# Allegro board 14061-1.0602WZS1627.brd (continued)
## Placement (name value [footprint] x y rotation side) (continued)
C4289  SC10U10V5KX-2DLGP  [C805H50]  120.18 18.92 270 bottom
C4290  SCD1U16V2KX-3DLGP  [C402H22]  129.74 41.54 0 top
C4291  SCD1U16V2KX-3DLGP  [C402H22]  138.96 38.69 270 top
C4292  SCD1U16V2KX-3DLGP  [C402H22]  138.96 37.81 270 top
C4293  SCD1U16V2KX-3DLGP  [C402H22]  138.96 36 270 top
C4294  SCD1U16V2KX-3DLGP  [C402H22]  138.96 33.28 270 top
C4295  SCD1U16V2KX-3DLGP  [C402H22]  138.96 32.39 270 top
C4296  SCD1U16V2KX-3DLGP  [C402H22]  138.96 34.2 270 top
C4297  SCD1U16V2KX-3DLGP  [C402H22]  138.96 36.89 270 top
C4298  SCD1U16V2KX-3DLGP  [C402H22]  138.96 35.09 270 top
C6701  SCD1U16V2KX-3DLGP  [C402H22]  81.77 78.05 180 top
C6702  SCD1U16V2KX-3DLGP  [C402H22]  87.28 79.86 180 top
C6703  SC10U6D3V3MX-GP  [C603H38]  86.32 74.17 90 top
C6710  SC10U6D3V3MX-DL-GP  [C603H36]  48.42 117.73 270 top
C6711  SCD1U16V2KX-3DLGP  [C402H22]  48.67 104.01 270 top
C6715  SC10P50V2JN-4GP  [C402H22]  30.5 7.03 0 top
C6716  SC22U6D3V3MX-1-DL-GP  [C603H40]  65.07 177.16 0 top
C6717  SC22U6D3V3MX-1-DL-GP  [C603H40]  63.87 177.16 0 top
C6718  SC22U6D3V3MX-1-DL-GP  [C603H40]  62.68 177.16 0 top
C6719  SC22U6D3V3MX-1-DL-GP  [C603H40]  88.77 162.95 0 bottom
C6720  SC22U6D3V3MX-1-DL-GP  [C603H40]  88.25 157.1 270 bottom
C6721  SC22U6D3V3MX-1-DL-GP  [C603H40]  93.17 165.07 90 bottom
C6722  SC22U6D3V3MX-1-DL-GP  [C603H40]  91.68 163.22 270 bottom
C6724  SCD01U25V2KX-3DLGP  [C402H22]  127.59 71.57 180 bottom
C6725  SCD1U10V2KX-4GP  [C402H20]  135.97 72.54 90 bottom
C6726  SC22U6D3V3MX-1-DL-GP  [C603H40]  62.93 199.49 180 top
C6727  SC22U6D3V3MX-1-DL-GP  [C603H40]  64.14 199.48 180 top
C6728  SC22U6D3V3MX-1-DL-GP  [C603H40]  65.38 199.47 180 top
C6729  SC22U6D3V3MX-1-DL-GP  [C603H40]  66.58 199.47 180 top
C6730  SC22U6D3V3MX-1-DL-GP  [C603H40]  61.66 199.46 180 top
C6731  SC22U6D3V3MX-1-DL-GP  [C603H40]  58.45 197.24 270 top
C6732  SCD1U16V2KX-3DLGP  [C402H22]  31.66 11.73 90 bottom
C6733  SCD1U16V2KX-3DLGP  [C402H22]  31.66 12.64 90 bottom
C6734  SCD1U16V2KX-3DLGP  [C402H22]  36.93 17.14 180 bottom
C12324  SCD1U50V3KX-DL-GP  [C603H35]  20.23 200.91 180 bottom
C12325  SCD1U50V3KX-DL-GP  [C603H35]  19.72 208.79 270 bottom
C12326  SC10U10V5KX-2DLGP  [C805H50]  19.57 214.38 180 top
C12327  SCD1U16V2KX-3DLGP  [C402H22]  17.97 207.14 0 top
C12328  SCD1U16V2KX-3DLGP  [C402H22]  48.67 104.02 90 bottom
C12329  SCD1U16V2KX-3DLGP  [C402H22]  48.44 88.01 270 top
C12330  SCD1U16V2KX-3DLGP  [C402H22]  48.67 104.9 90 bottom
C12331  SCD01U50V2KX-1DLGP  [C402H22]  47.02 92.96 0 top
C12332  SCD1U16V2KX-3DLGP  [C402H22]  48.67 105.79 90 bottom
C12333  SCD1U16V2KX-3DLGP  [C402H22]  48.67 103.12 90 bottom
C12334  SCD1U16V2KX-3DLGP  [C402H22]  64.42 104.52 180 bottom
C12335  SCD1U16V2KX-3DLGP  [C402H22]  48.22 108.31 180 bottom
C12336  SCD1U16V2KX-3DLGP  [C402H22]  48.49 100.6 270 top
C12338  SCD1U16V2KX-3DLGP  [C402H22]  48.49 98.8 270 top
C12339  SCD1U25V3KX-DLGP  [C603H36]  46.14 73.52 180 top
C12340  SCD1U25V3KX-DLGP  [C603H36]  44.9 73.52 180 top
C12341  SCD1U25V3KX-DLGP  [C603H36]  43.68 73.52 180 top
C12342  SCD01U50V2KX-1DLGP  [C402H22]  64.69 139.63 270 top
C12343  SCD1U16V2KX-3DLGP  [C402H22]  88.67 106.03 0 bottom
C12344  SCD1U16V2KX-3DLGP  [C402H22]  91.67 107.92 90 bottom
C12345  SCD1U16V2KX-3DLGP  [C402H22]  90.57 106.39 90 bottom
C12346  SCD1U16V2KX-3DLGP  [C402H22]  89.76 107.93 270 bottom
C12347  SCD1U16V2KX-3DLGP  [C402H22]  85.55 95.33 90 bottom
C12348  SCD1U16V2KX-3DLGP  [C402H22]  84.12 94.88 0 bottom
C12349  SCD01U50V2KX-1DLGP  [C402H22]  71.68 136.52 0 top
C12350  SC100P50V2JN-3DLGP  [C402H22]  26.82 23.06 270 bottom
CMCLR1  JOWLE-CON2-5-GP  [A2541WV0-1EX2PA-6T]  146.45 171.9 270 top
CMCLR2  JOWLE-CON2-5-GP  [A2541WV0-1EX2PA-6T]  150.6 181.4 270 top
CN1  PIN-CON4-SFP-GP  [210-41-04GB02]  148.37 85.57 270 top
CN2  ACES-CON4-37-GP  [88459-047N]  161.35 173.79 90 top
CONVT1  CLX-CON10-10-GP  [CI1410M1HRL-NH]  25 36.65 270 top
CPU2  BRASWELL-GP  [BGA1170M2725H57]  83 165 270 top
D1  1SS355-4-GP  [SOD323AKH38]  17.25 202.67 180 top
D5  BAS40C-2-GP  [SOT-23-9H44]  136.23 20.62 270 top
D6  RB551V30-GP  [SOD323AKH38]  135.78 16.51 0 top
D14  BAV99GP-GP  [SOT23-2D4-312H48]  45.4 29.59 270 top
D18  1SS355GP-GP  [SOD323AKH40]  114.92 62.65 90 bottom
D21  AZ2015-01H-GP  [SOD523AKH28]  152.66 52.88 0 bottom
D32  BX310F-R1-00000-GP  [D4724AKH44]  30.28 39.29 180 bottom
D33  1SS355-4-GP  [SOD323AKH38]  125.53 28.85 180 top
D34  BAT54A-12-GP  [SOT23-2D4-312H44]  103.13 105.54 0 top
D5209  BAT54A-12-GP  [SOT23-2D4-312H44]  102.8 87.78 90 top
DCIN1  DC-JACK345-GP  [2DC3115-000111F]  53.25 25.53 270 top
DCIN2  ACES-CONN14G-GP  [88314-077N]  54.75 34 180 top
DIMM1  DDR3-204P-262-GP-U  [AS0A621-J4R6-7H-U]  135.3 158.9 90 top
F1  POLYSW-1D5A6V-12-GP  [POLYSW-2114H30]  157.46 188.57 270 bottom
F2  POLYSW-2A6V-7-GP  [POLYSW-2114H30]  39.62 107.25 270 bottom
F3  POLYSW-1D5A6V-12-GP  [POLYSW-2114H30]  159.55 190.83 90 bottom
F4  POLYSW-1D5A6V-12-GP  [POLYSW-2114H30]  24.83 7.44 270 bottom
F6  POLYSW-1D5A8V-3-GP  [POLYSW-3217-UH40]  161.71 147.96 90 bottom
F13  POLYSW-1D5A6V-12-GP  [POLYSW-2114H30]  119.69 34.21 0 bottom
F14  POLYSW-2A6V-7-GP  [POLYSW-2114H30]  17.71 209.22 270 top
F16  FUSE-3A32V-26-GP  [FUSE-1608H22]  42.07 42.04 270 top
FANC3  FOX-CON4-30-GP  [HF1804H]  14 211 270 top
G5  COPPER-CLOSE-GP-U  [CON2C-U]  107.58 49.71 90 top
GPU1  SUN-S3-XT-GP  [BGA631M23H82]  83 100 90 top
H1  HOLE237R158-GP  [HOLE237R158]  94.38 192.31 180 top
H2  HOLE237R158-GP  [HOLE237R158]  62.39 165.12 180 top
H3  HOLE237R158-GP  [HOLE237R158]  94.38 137.93 180 top
H4  HOLE237R158-GP  [HOLE237R158]  69 123.75 180 top
H5  HOLE237R158-GP  [HOLE237R158]  94.39 76.25 180 top
H6  GEN8D5X8R5X4D5-8-F-A-GP  [GEN8D5X8R5X4D5-8-F-A]  165 225 270 top
H7  GEN315R138-8-F-A-1-GP  [GEN315R138-8-F-A-1]  5 160 180 top
H9  GEN8D5X8R5X4D5-8-F-A-GP  [GEN8D5X8R5X4D5-8-F-A]  25 49.15 0 top
H10  GEN315R178-8-F-A-3-GP  [GEN315R178-8-F-A-1]  165 20 180 top
H11  GEN315R138-8-F-A-2-S-GP  [GEN315R138-8-F-A-2-S]  172.5 64.43 180 top
HDD1  SKT-SATA7P-184-GP-U  [15-02070-5A61-A]  12 142 270 top
HDMI1  SKT-HDMI22-12-GP  [SKT-HDMI22-150077]  113.99 37.03 270 top
HDMI2  ARG-CON20-GP  [LVDFH-02004-TP00]  118.69 37.07 270 top
HS6  STF256R109H99-GP  [STF256R109H99]  144.25 214 180 top
L1  HCB2012KF-600T30-GP  [L20125H42]  36.04 107.43 270 bottom
L2  IND-2D2UH-250-GP-U  [L3030-2709H41]  31.83 104.65 0 bottom
L3  MHC1608S601LBP-GP  [L603H38]  155.86 104.7 270 bottom
L4  FILTER-4P-123-GP  [L125100-4P-1H36]  165.72 119.35 180 top
L5  FILTER-4P-123-GP  [L125100-4P-1H36]  165.9 117.09 180 top
L7  MHC1608S181NBP-GP  [L603H38]  134.6 68.71 270 top
L9  MHC1608S181NBP-GP  [L603H38]  118.42 51.38 90 bottom
L10  MHC1608S221NBP-GP  [L603H38]  152.76 37.97 90 top
L16  HCB1608KF-800T30-GP  [L603H38]  38.02 105.52 270 bottom
L17  HCB1608KF-800T30-GP  [L603H38]  32.71 78.28 270 bottom
L19  HCB1608KF-800T30-GP  [L603H38]  153.4 55.12 90 bottom
L20  MCB1005S121FBP-GP  [L402H24]  86.29 33.48 270 top
L21  MCB1005S121FBP-GP  [L402H24]  157.64 41.45 270 bottom
L22  BLM15BD102SN1D-GP  [L402H22]  47.73 22.07 0 top
L31  HCB2012KF-601T20-GP  [L20125H42]  143.9 23.6 0 top
L32  HCB2012KF-601T20-GP  [L20125H42]  145.93 23.6 0 top
L33  HCB2012KF-601T20-GP  [L20125H42]  150.27 22.78 0 top
L34  HCB2012KF-601T20-GP  [L20125H42]  148.12 22.78 0 top
L36  FILTER-4P-123-GP  [L125100-4P-1H36]  166.15 97.16 180 top
L37  FILTER-4P-123-GP  [L125100-4P-1H36]  166.15 94.87 180 top
L46  -  [0R0805-PAD]  119.82 37.77 180 bottom
L47  MCB1005S121FBP-GP  [L402H24]  90.76 99.44 90 bottom
L48  MCB1005S121FBP-GP  [L402H24]  86.95 110.16 180 bottom
L49  MCB1005S121FBP-GP  [L402H24]  74.61 81.89 180 top
L50  MCB1005S121FBP-GP  [L402H24]  79.43 87.61 90 bottom
L51  MCB1005S121FBP-GP  [L402H24]  73.34 81.89 180 top
L52  MHC1608S221NBP-GP  [L603H38]  93.48 96.32 0 bottom
L53  MHC1608S221NBP-GP  [L603H38]  94.13 108.21 180 bottom
L54  MCB1005S121FBP-GP  [L402H24]  157.61 194.74 0 top
L61  IND-33UH-85-GP  [L8080-6020H158]  34.82 38.66 270 top
L62  MCB1005S121FBP-GP  [L402H24]  84.26 33.45 270 top
L4101  BLM15HG102SN1D-GP  [L402H22]  143.19 70.05 270 bottom
L4102  MCB1005S121FBP-GP  [L402H24]  85.53 94.34 270 bottom
L4103  FILTER-4P-123-GP  [L125100-4P-1H36]  18.66 142.14 90 top
L4104  FILTER-4P-123-GP  [L125100-4P-1H36]  16.21 152.02 90 top
LED2  LED-O-23-GP  [LED1608AKH30]  170.07 91.45 180 top
LOUT1  AUDIO-JK419-GP  [JAC331-0140A8B-9H]  76.93 37.66 90 top
LPC1  FOX-CONN14A-S1-GP  [HL5507F]  109.63 74.7 0 top
LVDS1  ACES-CON30-21-GP  [50524-0300N-001]  36.8 95 270 top
MEM1  H5TQ1G63DFR-11C-1-GP  [BGA96D075130H48]  55.61 111.68 0 top
MEM2  H5TQ1G63DFR-11C-1-GP  [BGA96D075130H48]  55.61 91.62 180 top
MEM3  H5TQ1G63DFR-11C-1-GP  [BGA96D075130H48]  55.61 111.68 180 bottom
MEM4  H5TQ1G63DFR-11C-1-GP  [BGA96D075130H48]  55.61 91.62 0 bottom
MEMCD1  SKT-SDCARD-52-GP  [156-5101902601]  174.65 144.79 90 top
NGFF1  SKT-MINI67P-3-GP-U1  [2199230-7]  116 214 270 top
NOREF  -  [unnamed]  178.22 223.03 0 top
NOREF#2  -  [#2]  70.26 205.61 0 top
NOREF#3  *  [unnamed]  65.72 5.8 0 top
NOREF#4  *  [unnamed]  17.69 223.98 0 top
NOREF#5  *  [unnamed]  164.75 61.21 0 top
NOREF#6  -  [#2]  113.73 178.94 0 top
NOREF#7  -  [unnamed]  171.63 4.95 0 top
NOREF#8  -  [#2]  66.2 224.16 0 top
NOREF#9  -  [#2]  135.03 219.33 0 top
NOREF#10  -  [#2]  -10 0 0 top
NOREF#11  *  [unnamed]  156.62 225.43 0 top
NOREF#12  -  [unnamed]  152.94 226.06 0 top
NOREF#13  -  [#2]  0 103.25 0 top
NOREF#14  -  [#2]  -509.06 -10.18 0 top
NOREF#15  -  [unnamed]  11.57 4.95 0 top
NOREF#16  -  [#2]  -10 0 0 top
NOREF#17  *  [unnamed]  155.99 17.12 0 top
NOREF#18  *  [unnamed]  171.63 8.45 0 top
NOREF#19  *  [unnamed]  102.01 185.55 0 top
NOREF#20  -  [unnamed]  6 10.67 0 top
NOREF#21  -  [unnamed]  185.45 223.65 0 top
NOREF#22  -  [unnamed]  94.14 12.32 0 top
NOREF#23  -  [#2]  -251.47 -3.7 0 top
NOREF#24  -  [unnamed]  183.93 6.22 0 top
NOREF#25  *  [unnamed]  104.17 47.88 0 top
NOREF#26  *  [unnamed]  5.05 6.01 0 top
NOREF#27  -  [#2]  -10 0 0 top
NOREF#28  *  [unnamed]  45.7 131.72 0 top
NOREF#29  *  [unnamed]  178.33 217.98 0 top
NOREF#30  *  [unnamed]  84.41 64.52 180 bottom
NOREF#31  *  [unnamed]  65.72 5.8 180 bottom
NOREF#32  *  [unnamed]  149.26 8.26 180 bottom
NOREF#33  *  [unnamed]  5.05 6.01 180 bottom
NOREF#34  -  [#2]  114.18 177.47 90 bottom
NOREF#35  *  [unnamed]  178.33 217.98 180 bottom
NOREF#36  *  [unnamed]  42.4 140.23 180 bottom
NOREF#37  *  [unnamed]  10.83 219.71 180 bottom
NOREF#38  -  [#2]  178.58 28.52 90 bottom
NOREF#39  *  [unnamed]  156.62 225.43 180 bottom
NOREF#40  *  [unnamed]  171.63 8.45 180 bottom
ODD1  SKT-SATA7P-184-GP-U  [15-02070-5A61-A]  8.35 177 270 top
OSC2  OSC-48MHZ-16GP  [SMD-OSC8H52]  132.9 72.13 180 top
PC1  SC1U10V2KX-1DLGP  [C402H22]  127.29 212.47 90 bottom
PC4  SC22P50V2JN-4DLGP  [C402H22]  132.48 79.95 90 bottom
PC5  SCD22U25V3KX-GP  [C603H40]  135.2 80.4 180 bottom
PC6  SC150P50V2JN-3DLGP  [C402H22]  130.94 76.38 0 top
PC7  SC1KP50V2KX-1DLGP  [C402H22]  130.44 77.77 90 top
PC8  SC33P50V2JN-3DLGP  [C402H22]  132.39 77.77 90 top
PC9  SCD01U50V2KX-1GP  [C402H22]  129.25 80.94 0 bottom
PC11  SC390P50V2KX-1-GP  [C402H22]  137.93 79.86 180 top
PC12  SCD1U25V3KX-GP  [C603H36]  121.24 79.78 270 top
PC13  SC330P50V2KX-3-DL-GP  [C402H22]  135.77 81.23 180 top
PC14  SCD01U50V2KX-1GP  [C402H22]  137.7 83.64 90 top
PC15  SCD033U25V2KX-1-GP  [C402H22]  139.35 86.08 0 top
PC16  SCD22U25V3KX-DL-GP  [C603H36]  140.42 86.46 0 top
PC17  SC1U16V3KX-4DLGP  [C603H36]  129.12 88.16 180 top
PC18  SC1U16V3KX-4DLGP  [C603H36]  127.92 88.16 180 top
PC19  SCD22U25V3KX-DL-GP  [C603H36]  132.93 88.21 180 top
PC20  SCD1U50V3KX-DL-GP  [C603H35]  141.61 84.94 0 top
PC21  SC10U10V5KX-2DLGP  [C805H50]  30.01 183.85 0 top
PC22  SC1U16V3KX-4DLGP  [C603H36]  28.4 183.97 0 top
PC23  SC1500P50V3KX-DLGP  [C603H36]  29.55 208.79 180 top
PC24  SC10U25V6KX-4DL-GP  [C1206H71]  140.32 97.22 180 bottom
PC27  SCD1U16V2KX-3DLGP  [C402H22]  166.23 89.15 180 bottom
PC28  SCD1U50V3KX-DL-GP  [C603H35]  29.75 215.72 270 top
PC29  SC10U25V6KX-4DL-GP  [C1206H71]  28.79 222.07 270 top
PC31  SC10U25V6KX-4DL-GP  [C1206H71]  28.79 219.79 270 top
PC32  SC10U25V6KX-4DL-GP  [C1206H71]  28.79 217.5 270 top
PC33  SC1U16V3KX-4DLGP  [C603H36]  22.13 218.8 270 top
PC34  SCD1U50V3KX-DL-GP  [C603H35]  22.16 220.5 270 top
PC41  SC22P50V2JN-L-GP  [C402H22]  10.17 220.98 90 top
PC58  SC1U16V3KX-4DLGP  [C603H36]  133.45 82.51 180 bottom
PC59  SCD1U16V3KX-3GP  [C603H36]  137.32 84.61 0 bottom
PC60  SCD22U25V3KX-DL-GP  [C603H36]  136.48 87.66 90 top
PC61  SC10U25V6KX-4DL-GP  [C1206H71]  138.11 97.21 0 top
PC68  SC27P50V2JN-2DLGP  [C402H22]  51.71 130.75 90 top
PC124  SC22P50V2JN-4GP  [C402H22]  162.88 206.25 180 bottom
PC151  SCD1U16V2KX-3DLGP  [C402H22]  63.09 128.83 90 top
PC163  SC1U10V2KX-1DLGP  [C402H22]  29.03 9.98 180 bottom
PC2127  SC470P50V2KX-3DLGP  [C402H22]  152.26 21.41 270 top
PC4201  SC1U50V5KX-DL-GP  [C805H54]  65.21 30.62 90 top
PC4202  SCD1U25V3KX-DLGP  [C603H36]  63.53 33.12 270 bottom
PC4203  SCD1U25V3KX-DLGP  [C603H36]  63.53 31.93 270 bottom
PC4204  SCD1U50V3KX-DL-GP  [C603H35]  63.53 29.59 90 bottom
PC4301  SC10P50V2JN-4DLGP  [C402H22]  45.45 69.94 180 bottom
PC4302  SCD1U50V3KX-DL-GP  [C603H35]  35.45 74.98 180 top
PC4303  SC2200P50V2KX-2DLGP  [C402H22]  34.39 74.67 180 top
PC4304  SC470P50V2KX-3DLGP  [C402H22]  32.59 62.16 90 bottom
PC4305  SC10P50V2JN-4DLGP  [C402H22]  45.45 71.87 0 bottom
PC4401  SC10U25V5KX-DL-GP  [C805H58]  39.07 74.62 90 top
PC4402  SCD1U50V3KX-DL-GP  [C603H35]  45.37 62.56 90 top
PC4403  SCD1U50V3KX-DL-GP  [C603H35]  44.05 64.92 270 top
PC4404  SCD1U50V3KX-DL-GP  [C603H35]  44.05 63.73 270 top
PC4405  SCD1U25V2KX-1-DL-GP  [C402H22]  37.8 52.54 90 top
PC4406  SC10U25V5KX-DL-GP  [C805H58]  37.9 51.1 90 top
PC4407  SC10U25V5KX-DL-GP  [C805H58]  37.89 51.09 270 bottom
PC4408  SC1U50V5KX-DL-GP  [C805H54]  43.57 60.55 0 bottom
PC4409  SCD1U10V2KX-4DLGP  [C402H22]  79.31 213.36 180 top
PC4410  SCD1U10V2KX-4DLGP  [C402H22]  80.55 213.36 180 top
PC4411  SC330P50V2KX-3-DL-GP  [C402H22]  86.39 217.93 270 bottom
PC4412  SC47P50V2JN-5DLGP  [C402H22]  83.85 218.31 180 bottom
PC4413  SC2200P50V2KX-2DLGP  [C402H22]  84.36 219.84 270 bottom
PC4414  SC1KP16V2KX-DL-GP  [C402H22]  85.21 214.57 90 top
PC4415  SC3300P50V2KX-1DLGP  [C402H22]  82.28 216.05 270 top
PC4416  SCD1U16V2KX-3DLGP  [C402H22]  76.11 217.7 270 top
PC4417  SC470P50V2KX-3DLGP  [C402H22]  80.63 218.54 0 top
PC4418  SC1KP50V2KX-1DLGP  [C402H22]  79.74 218.54 0 top
PC4419  SC560P50V2KX-2DLGP  [C402H22]  77.88 223.29 270 top
PC4420  SC2200P50V2KX-2DLGP  [C402H22]  79.66 221.36 270 bottom
PC4421  SCD22U25V3KX-DL-GP  [C603H36]  73.54 215.39 270 bottom
PC4423  SCD1U50V3KX-DL-GP  [C603H35]  60.03 215.74 270 bottom
PC4424  SC10U25V6KX-4DL-GP  [C1206H71]  60.1 216.08 90 top
PC4426  SC2D2U10V3KX-1DLGP-U  [C603H36]  76.61 220.98 0 bottom
PC4427  SCD01U50V2KX-1DLGP  [C402H22]  77.88 214.02 90 top
PC4428  SC1U10V2KX-1DLGP  [C402H22]  84.28 212.04 180 bottom
PC4429  SC1KP50V3KX-DLGP  [C603H36]  67.65 212.83 0 bottom
PC4509  SCD1U10V2KX-4DLGP  [C402H22]  23.5 161.82 270 bottom
PC4510  SCD1U10V2KX-4DLGP  [C402H22]  23.5 162.86 270 bottom
PC4511  SC330P50V2KX-3-DL-GP  [C402H22]  26.82 169.34 270 top
PC4512  SC47P50V2JN-5DLGP  [C402H22]  30.69 167.35 90 top
PC4513  SCD01U50V2KX-1DLGP  [C402H22]  29.18 167.91 0 top
PC4514  SC1KP16V2KX-DL-GP  [C402H22]  22.13 167.89 180 top
PC4515  SC3300P50V2KX-1DLGP  [C402H22]  24.16 167.89 180 top
PC4516  SCD1U16V2KX-3DLGP  [C402H22]  28.07 157.76 180 top
PC4517  SC470P50V2KX-3DLGP  [C402H22]  28.18 164.8 90 bottom
PC4518  SC1KP50V2KX-1DLGP  [C402H22]  31.78 161.54 90 top
PC4519  SC1800P50V2KX-1-DL-GP  [C402H22]  31.53 162.94 0 top
PC4520  SC2200P50V2KX-2DLGP  [C402H22]  32.42 162.94 180 top
PC4521  SCD22U25V3KX-DL-GP  [C603H36]  24.09 156.79 180 top
PC4523  SCD1U50V3KX-DL-GP  [C603H35]  24.9 146.66 180 bottom
PC4524  SC10U25V6KX-4DL-GP  [C1206H71]  23.15 146.94 0 bottom
PC4526  SC2D2U10V3KX-1DLGP-U  [C603H36]  30.44 157.12 0 top
PC4527  SCD01U25V2KX-3DLGP  [C402H22]  23.5 160.91 270 bottom
PC4528  SC1U10V2KX-1DLGP  [C402H22]  24.22 164.88 270 bottom
PC4529  SC1KP50V3KX-DLGP  [C603H36]  26.14 154.79 90 bottom
PC4701  SCD1U10V2KX-4DLGP  [C402H22]  137.32 109.58 270 top
PC4702  SC1U10V2KX-1DLGP  [C402H22]  130.52 114.33 270 top
PC4703  SCD1U50V3KX-DL-GP  [C603H35]  131.07 111.58 90 top
PC4704  SC1KP50V3KX-DLGP  [C603H36]  127.16 114.5 90 top
PC4705  SC22P50V2JN-4DLGP  [C402H22]  136.86 115.42 180 top
PC4706  SC10U25V6KX-4DL-GP  [C1206H71]  128.3 108.66 180 top
PC4707  SCD1U16V2KX-3DLGP  [C402H22]  118.57 115.57 180 top
PC4708  SC10U10V5KX-2DLGP  [C805H50]  120.05 115.47 180 top
PC4801  SCD1U10V2KX-4DLGP  [C402H22]  99.3 217.54 90 top
PC4901  SC10U25V6KX-4DL-GP  [C1206H71]  72.42 53.29 180 top
PC4902  SC10U25V6KX-4DL-GP  [C1206H71]  70.14 53.29 180 top
PC4903  SC10U25V6KX-4DL-GP  [C1206H71]  72.65 64.72 0 bottom
PC4904  SC10U25V6KX-4DL-GP  [C1206H71]  70.24 64.72 0 bottom
PC4905  SC1U10V2KX-1DLGP  [C402H22]  96.81 56.52 180 top
PC4906  SC1U10V2KX-1DLGP  [C402H22]  97.57 58.42 90 top
PC4907  SC1KP50V3KX-DLGP  [C603H36]  74 58.29 270 top
PC4908  SC1KP50V3KX-DLGP  [C603H36]  74.46 70.23 270 top
PC4909  SC22P50V2JN-4DLGP  [C402H22]  57.39 61.14 0 top
PC4910  SC22P50V2JN-4DLGP  [C402H22]  57.23 56.95 0 top
PC4911  SC18P50V2JN-1DLGP  [C402H22]  60.65 61.81 270 bottom
PC4912  SC18P50V2JN-1DLGP  [C402H22]  60.86 57.95 270 bottom
PC4913  SCD1U50V3KX-DL-GP  [C603H35]  63.28 54.15 0 top
PC4914  SCD1U50V3KX-DL-GP  [C603H35]  62.69 65.2 0 top
PC4915  SC1U16V2KX-DL-GP  [C402H22]  58.4 63.07 180 top
PC4916  SCD1U50V3KX-DL-GP  [C603H35]  64.65 54.69 180 top
PC4917  SC4D7U6D3V3KX-DLGP  [C603H36]  68.26 59.69 90 top
PC4918  SC4D7U6D3V3KX-DLGP  [C603H36]  63.96 64.4 180 top
PC5001  SC10U25V6KX-4DL-GP  [C1206H71]  152.89 145.34 270 bottom
PC5002  SC22P50V2JN-4DLGP  [C402H22]  145.35 131.11 0 top
PC5003  SC1U10V2KX-1DLGP  [C402H22]  155.37 136.09 90 top
PC5004  SC1U10V2KX-1DLGP  [C402H22]  155.76 134.44 180 top
PC5005  SC10U10V5KX-2DLGP  [C805H50]  146.47 135.13 270 top
PC5006  SC10U10V5KX-2DLGP  [C805H50]  146.47 137.18 270 top
PC5007  SCD033U16V2KX-DLGP  [C402H22]  149.99 134.01 0 bottom
PC5008  SCD1U50V3KX-DL-GP  [C603H35]  153.47 139.29 0 top
PC5009  SC1KP50V3KX-DLGP  [C603H36]  152.86 149.35 270 bottom
PC5010  SC10U25V6KX-4DL-GP  [C1206H71]  152.89 147.6 270 bottom
PC5011  SCD1U16V2KX-3DLGP  [C402H22]  154.72 167.16 180 top
PC5012  SC22U6D3V3MX-1-DL-GP  [C603H40]  153.63 167.49 180 top
PC5112  SC10U6D3V3MX-DL-GP  [C603H36]  170.49 83.54 90 bottom
PC5113  SC1U25V3KX-1-DLGP  [C603H36]  164.17 88.85 90 bottom
PC5114  SC100P50V2JN-3GP  [C402H22]  165.16 78.79 270 bottom
PC5115  SC10U6D3V3MX-GP  [C603H38]  162.83 79.8 90 bottom
PC5116  SC10U6D3V3MX-DL-GP  [C603H36]  162.82 78.59 270 bottom
PC5211  SCD1U10V2KX-4DLGP  [C402H22]  45.93 222.12 270 top
PC5212  SC10U6D3V3MX-DL-GP  [C603H36]  40.62 177.19 0 top
PC5213  SC1U25V3KX-1-DLGP  [C603H36]  38.39 172.39 270 top
PC5215  SC10U6D3V3MX-GP  [C603H38]  48.17 176.5 180 top
PC5216  SC10U6D3V3MX-DL-GP  [C603H36]  46.95 176.5 0 top
PC5217  SCD1U10V2KX-5DLGP  [C402H22]  39.23 168.81 0 top
PC5219  SC100P50V2JN-3GP  [C402H22]  48.47 172.26 0 top
PC5221  SC22P50V2GN-GP  [C402H22]  168.46 88.65 90 bottom
PC5222  SCD1U10V2KX-4DLGP  [C402H22]  37.57 167.11 270 top
PC5223  SC10U6D3V3MX-DL-GP  [C603H36]  23.71 182.75 0 top
PC5224  SC1U25V3KX-1-DLGP  [C603H36]  19.59 177.88 0 top
PC5225  SC10U6D3V3MX-DL-GP  [C603H36]  36.61 177.95 270 top
PC5226  SC100P50V2JN-3GP  [C402H22]  34.73 177.64 0 top
PC5227  SC10U6D3V3MX-GP  [C603H38]  36.61 179.15 90 top
PC5228  SC22P50V2GN-GP  [C402H22]  22.54 173.3 270 top
PC5229  SCD1U16V2KX-3DLGP  [C402H22]  22.54 176.35 270 top
PC5232  SCD01U50V2KX-1DLGP  [C402H22]  53.63 63.88 270 bottom
PC5233  SC1U10V2KX-1DLGP  [C402H22]  44.69 54.48 180 top
PC5234  SCD1U50V3KX-DL-GP  [C603H35]  43.59 59.44 90 top
PC5235  SC1KP50V2KX-1DLGP  [C402H22]  42.12 72.41 180 top
PC5236  SCD1U50V3KX-DL-GP  [C603H35]  49.08 55.64 90 top
PC5237  SC470P50V2KX-3DLGP  [C402H22]  46.01 53.74 0 top
PC5238  SCD1U25V2KX-1-DL-GP  [C402H22]  50.49 53.99 0 top
PC5239  SC220P50V2KX-3DLGP  [C402H22]  53.63 61.72 270 bottom
PC5240  SC10U25V5KX-DL-GP  [C805H58]  31.02 74.86 180 top
PC5241  SC10U25V5KX-DL-GP  [C805H58]  32.97 74.85 180 top
PC5242  SCD1U50V3KX-DL-GP  [C603H35]  36.67 74.98 180 top
PC5243  SCD1U10V2KX-4DLGP  [C402H22]  101.53 119.02 0 top
PC5251  SCD1U10V2KX-4DLGP  [C402H22]  126.07 216.48 90 bottom
PC5254  SCD1U10V2KX-4DLGP  [C402H22]  125.2 219.96 180 bottom
PC5255  SCD1U10V2KX-4DLGP  [C402H22]  142.04 126.26 180 bottom
PC5256  SCD1U10V2KX-4DLGP  [C402H22]  141.1 126.26 180 bottom
PC5257  SC10U6D3V3MX-DL-GP  [C603H36]  93.18 220.83 0 top
PC5258  SC10U6D3V3MX-DL-GP  [C603H36]  97.11 204.85 90 top
PC5259  SC1U10V2KX-1DLGP  [C402H22]  96.17 223.93 180 top
PC5260  SC10U6D3V3MX-DL-GP  [C603H36]  91.91 220.83 0 top
PC5261  SC10U6D3V3MX-DL-GP  [C603H36]  97.11 206.12 90 top
PC5262  SC22P50V2JN-4DLGP  [C402H22]  100.31 222.86 180 top
PC5263  SC1KP50V3KX-DLGP  [C603H36]  89.95 219.19 180 top
PC5264  SCD1U16V2KX-3DLGP  [C402H22]  97.11 207.26 90 top
PC5265  SC680P50V2KX-2DLGP  [C402H22]  98.25 223.9 180 top
PC5266  SCD1U10V2KX-4DLGP  [C402H22]  98.8 218.94 180 top
PC5267  SC1500P50V3KX-DLGP  [C603H36]  133.06 97.57 90 top
PC5268  SC330P50V2KX-3-DL-GP  [C402H22]  139.45 80.37 90 top
PC5269  SC10U25V6KX-4DL-GP  [C1206H71]  140.32 97.22 0 top
PC5270  SC10U25V6KX-4DL-GP  [C1206H71]  138.11 97.21 180 bottom
PC5271  SCD01U50V2KX-1DLGP  [C402H22]  87.44 93.48 90 bottom
PC5272  SC1KP50V2KX-1DLGP  [C402H22]  137.97 81.45 90 top
PC5273  SCD1U50V3KX-DL-GP  [C603H35]  136.39 97.23 180 top
PC5430  SC10U10V5KX-2DLGP  [C805H50]  48.04 84.12 270 top
PC5431  SC10U10V5KX-2DLGP  [C805H50]  56.07 134.08 180 top
PC5432  SC10U10V5KX-2DLGP  [C805H50]  58.07 134.09 180 top
PC5433  SCD1U16V2KX-3DLGP  [C402H22]  61.68 131.4 180 top
PC5434  SC10U10V5KX-2DLGP  [C805H50]  48.04 82.17 270 top
PC5435  SC1U25V3KX-1-DLGP  [C603H36]  62.86 127.77 90 top
PC5436  SCD1U10V2KX-4DLGP  [C402H22]  138.95 112.73 180 top
PC5439  SC10U10V5KX-2DLGP  [C805H50]  52.87 193.65 180 top
PC5440  SCD1U16V2KX-3DLGP  [C402H22]  52.53 190.47 90 top
PC5441  SC10U25V6KX-4DL-GP  [C1206H71]  42.76 205.72 270 top
PC5442  SCD1U50V3KX-DL-GP  [C603H35]  40.06 216.15 180 top
PC5443  SC1U10V2KX-1DLGP  [C402H22]  38.79 216.53 0 top
PC5444  SCD1U10V2KX-4DLGP  [C402H22]  42.78 220.6 0 top
PC5445  SC1KP50V3KX-DLGP  [C603H36]  37.45 205.44 180 top
PC5446  SC22P50V2JN-4DLGP  [C402H22]  36.77 223.08 90 top
PC5447  SC1U25V3KX-1-DLGP  [C603H36]  57.08 73.43 180 top
PD4202  P6SBMJ24AGP-GP  [D5436AKH97]  60.45 23.15 180 top
PD4401  RB520SM-30T2R-GP  [D1608-035030AKH28]  43.21 55.63 180 top
PD4405  1N4148WS-7-F-GP  [SOD323AKH42]  54.74 70.64 90 top
PG3  GAP-CLOSE  [CON2C]  116.97 95.17 270 top
PG4  GAP-CLOSE  [CON2C]  123.2 95.17 90 top
PG4401  GAP-CLOSE  [CON2C]  59.75 203.66 180 bottom
PG4402  GAP-CLOSE  [CON2C]  59.82 201.27 0 bottom
PG4501  GAP-CLOSE  [CON2C]  39.02 152.17 0 top
PG4502  GAP-CLOSE  [CON2C]  39.02 145.95 180 top
PG4901  GAP-CLOSE-PWR-3-GP  [GAP-CLOSE-PWR-3]  66.45 59.56 270 top
PG4902  GAP-CLOSE-PWR-3-GP  [GAP-CLOSE-PWR-3]  92.79 48.16 90 top
PG4903  GAP-CLOSE-PWR-3-GP  [GAP-CLOSE-PWR-3]  97.24 71.53 180 top
PG4904  GAP-CLOSE-PWR-3-GP  [GAP-CLOSE-PWR-3]  65.42 61.58 0 top
PG4905  GAP-CLOSE-PWR-3-GP  [GAP-CLOSE-PWR-3]  51.54 48.13 90 top
PG4906  GAP-CLOSE-PWR-3-GP  [GAP-CLOSE-PWR-3]  40.65 64.76 180 top
PG4907  GAP-CLOSE-PWR-3-GP  [GAP-CLOSE-PWR-3]  53.3 48.15 90 top
PG4908  GAP-CLOSE-PWR-3-GP  [GAP-CLOSE-PWR-3]  40.65 65.77 180 top
PL1  IND-D36UH-19-GP  [L115100-2H158]  120.15 95.17 270 top
PL3  IND-1D5UH-52-GP  [L115100-2030H158]  30.13 199.95 0 top
PL4301  MLVS0402M04-GP-U  [L402H24]  32.59 63.17 90 bottom
PL4302  MLVS0402M04-GP-U  [L402H24]  46.4 71.86 0 bottom
PL4303  MLVS0402M04-GP-U  [L402H24]  46.4 69.96 180 bottom
PL4401  IND-D33UH-7-GP  [L736630H119]  59.63 202.49 180 bottom
PL4501  IND-D36UH-19-GP  [L115100-2H158]  39.12 149.1 0 top
PL4701  IND-1D5UH-53-GP  [L686647H119]  117.43 108.94 180 top
PL4903  IND-3D3UH-116-GP  [L686647H119]  83.85 53.34 180 top
PL4904  IND-2D2UH-122-GP  [L686647H119]  83.65 65.23 0 top
PL5002  IND-1D5UH-53-GP  [L686647H119]  156.8 161.49 90 top
PL5003  IND-5D6UH-48-GP-U1  [L7066-1830-UH119]  38.17 62.82 0 bottom
PL5004  IND-1D5UH-53-GP  [L686647H119]  94.47 213.01 270 top
PL47001  IND-1D5UH-53-GP  [L686647H119]  40.24 194.72 270 top
PN4401  NTC-100K-20-GP  [NTC-402H24-U]  52.99 210.44 180 bottom
PN4402  NTC-100K-20-GP  [NTC-402H24-U]  55.23 202.26 180 bottom
PN4501  NTC-100K-20-GP  [NTC-402H24-U]  28.35 139.95 270 bottom
PN4502  NTC-100K-20-GP  [NTC-402H24-U]  35.8 156.82 270 top
PQ7  SIR172ADP-T1-GE3-GP  [PPAK-5PH45]  33.69 211.86 0 top
PQ8  SIRA12DP-T1-GE3-GP  [PPAK-5PH45]  25.41 209.8 180 top
PQ4204  PDTC124EU-1-GP  [SOT323CBE2D2H44]  69.89 37.47 180 top
PQ4205  PDTA124EU-1-GP  [SOT323CBE2D2H44]  70.39 29.7 90 top
PQ4206  2N7002K-2-GP  [SOT23DGS2D4H44]  69.14 44.65 270 top
PQ4401  AON6520-GP  [PPAK-8P-5262H40]  57.02 211.93 180 bottom
PQ4402  AON6510-GP  [PPAK-8P-5262H40]  63.57 210.17 0 bottom
PQ4406  2N7002KDW-GP  [SOT-363H44]  54.54 73.25 270 top
PQ4408  2N7002K-2-GP  [SOT23DGS2D4H44]  49.06 65.15 90 bottom
PQ4409  MMBT3906-4-GP  [SOT23CBE2D4H44]  50.76 71.98 90 top
PQ4701  AON7410-GP  [PPAK-8P-3232H36]  125.26 106.78 270 top
PQ4702  AON7506-GP  [PPAK-8P-3232H36]  123.76 111.2 90 top
PQ4901  AON7410-GP  [PPAK-8P-3232H36]  75.52 50.55 90 top
PQ4902  AON7506-GP  [PPAK-8P-3232H36]  77.22 66.95 270 top
PQ4903  AON7410-GP  [PPAK-8P-3232H36]  77.05 54.99 270 top
PQ4904  AON7410-GP  [PPAK-8P-3232H36]  75.7 62.38 90 top
PQ5001  AON6520-GP  [PPAK-8P-5262H40]  149.54 151.76 180 top
PQ5002  AON6510-GP  [PPAK-8P-5262H40]  156.12 153.52 0 top
PQ5003  2N7002A-7-GP  [SOT23DGS2D4H48]  55.53 56.01 270 bottom
PQ5004  2N7002A-7-GP  [SOT23DGS2D4H48]  53.93 62.69 270 top
PQ5005  NTJD512NT1G-GP  [SOT-363H44]  47.28 40.13 0 top
PQ5006  2N7002KDW-GP  [SOT-363H44]  49.49 67.92 270 top
PQ47001  AON7410-GP  [PPAK-8P-3232H36]  44.81 202.72 0 top
PQ47002  AON7506-GP  [PPAK-8P-3232H36]  40.24 201.19 180 top
PR1  0R2J-2-GP  [R402H16]  130.26 80.94 180 bottom
PR2  -  [0R0402-PAD]  128.41 84.58 90 bottom
PR3  1KR2J-1-GP  [R402H16]  128.35 76.53 0 top
PR4  1KR2J-1-GP  [R402H16]  125.26 76.33 90 top
PR5  10KR2F-2-GP  [R402H16]  158.33 210.46 180 bottom
PR6  1K91R2F-1-GP  [R402H16]  123.58 76.63 180 top
PR7  1KR2J-1-GP  [R402H16]  121.47 77.8 270 top
PR8  47KR2F-GP  [R402H16]  132.39 76.76 90 top
PR9  47KR2F-GP  [R402H16]  128.23 80.94 0 bottom
PR10  -  [0R0402-PAD]  127.41 78 270 top
PR11  0R0402-PAD-2-GP  [0R0402-PAD-1]  133.87 78.23 180 top
PR12  0R2J-2-GP  [R402H16]  135.8 79.32 180 top
PR13  8K06R2F-GP  [R402H16]  129.93 76.38 0 top
PR14  -  [0R0402-PAD]  125.41 77.95 270 top
PR15  1KR2J-1-GP  [R402H16]  118.05 78.92 90 top
PR16  1K21R2F-2-GP  [R402H16]  137.7 82.68 270 top
PR17  -  [0R0402-PAD]  124.26 79.1 90 top
PR18  -  [0R0402-PAD]  124.26 80.14 90 top
PR19  10KR2F-2-GP  [R402H16]  118.05 79.98 90 top
PR20  562R2F-GP  [R402H16]  137.42 78.38 90 top
PR21  1K87R2F-GP  [R402H16]  136.91 79.86 180 top
PR23  -  [0R0402-PAD]  124.26 81.36 90 top
PR25  -  [0R0402-PAD]  123.97 82.4 90 top
PR26  1KR2J-1-GP  [R402H16]  121.93 82.42 270 top
PR28  -  [0R0402-PAD]  86.82 92.08 180 bottom
PR29  -  [0R0402-PAD]  87.89 92.1 180 bottom
PR30  -  [0R0402-PAD]  123.99 83.44 90 top
PR31  1KR2J-1-GP  [R402H16]  121.98 83.79 270 top
PR32  -  [0R0402-PAD]  124.02 84.51 90 top
PR33  1KR2J-1-GP  [R402H16]  122.05 85.5 270 top
PR34  82D5R2F-1-GP  [R402H16]  137.27 85.04 0 top
PR35  -  [0R0402-PAD]  124.26 85.55 90 top
PR36  -  [0R0805-PAD]  32.83 188.75 90 top
PR37  -  [0R0805-PAD]  32.83 190.78 90 top
PR38  -  [0R0805-PAD]  32.84 188.74 270 bottom
PR39  2D2R5J-1-GP  [R805H24]  34.02 210.06 180 bottom
PR40  10KR2J-3-GP  [R402H16]  168.23 90.63 90 bottom
PR41  2D2R5J-1-GP  [R805H24]  29.55 213.08 180 top
PR42  2K61R2F-1-GP  [R402H16]  142.2 89.15 90 top
PR43  2D2R3-1-U-GP  [R603H22]  134.12 88.21 180 top
PR44  -  [0R0402-PAD]  126.73 87.96 180 top
PR45  3K65R3F-GP  [R603H22]  142.53 87.99 90 top
PR46  -  [0R0805-PAD]  33.1 223.37 0 bottom
PR47  -  [0R0805-PAD]  31.08 223.36 0 bottom
PR48  2D2R5J-1-GP  [R805H24]  20.4 217.17 90 top
PR50  2D2R5J-1-GP  [R805H24]  21.95 222.33 90 top
PR51  NTC-10K-27-GP-U  [NTC-402H24-U]  117.69 101.27 270 top
PR53  470KR2F-GP  [R402H16]  11.88 218.5 0 top
PR57  51KR2J-1-GP  [R402H16]  11.54 222.05 270 top
PR58  10KR2F-2-GP  [R402H16]  11.87 220.47 180 top
PR59  15K8R2F-GP  [R402H16]  10.17 219.96 90 top
PR60  NTC-470K-9-GP-U  [NTC-402H24-U]  134.7 105.36 270 top
PR77  10KR2F-2-GP  [R402H16]  54.13 132.8 90 top
PR78  6K98R2F-GP  [R402H16]  51.7 131.73 90 top
PR79  10R2F-L-GP  [R402H14]  51.71 129.76 90 top
PR96  1KR2J-1-GP  [R402H16]  118.91 82.68 90 top
PR101  -  [0R0402-PAD]  136.18 88.82 270 top
PR102  1KR2J-1-GP  [R402H16]  117.61 86.89 90 top
PR103  1KR2J-1-GP  [R402H16]  117.61 88.01 90 top
PR211  -  [0R0805-PAD]  32.84 190.76 270 bottom
PR212  -  [0R0805-PAD]  32.83 184.84 90 top
PR213  -  [0R0805-PAD]  32.83 186.79 90 top
PR225  10KR2J-3-GP  [R402H16]  63.09 129.85 270 top
PR1689  12K4R2F-GP  [R402H16]  33.71 177.66 0 top
PR4204  240KR3-GP  [R603H22]  64.29 28.94 90 top
PR4207  47KR3J-L-GP  [R603H22]  67.01 28.98 90 top
PR4210  1KR2J-1-GP  [R402H16]  70.62 41.23 0 top
PR4214  3K3R6J-GP  [R1206H28]  69.6 32.38 90 top
PR4401  1KR2J-1-GP  [R402H16]  79.43 211.25 180 top
PR4402  10KR2J-3-GP  [R402H16]  80.55 211.25 180 top
PR4403  10KR2J-3-GP  [R402H16]  81.57 213.36 180 top
PR4404  47R2F-GP  [R402H16]  86.27 216.79 90 bottom
PR4405  1KR2F-3-GP  [R402H16]  84.36 216.79 270 bottom
PR4406  560KR2F-GP  [R402H16]  86.39 218.95 270 bottom
PR4407  3K3R2F-2-GP  [R402H16]  84.87 218.31 180 bottom
PR4410  0R0402-PAD-2-GP  [0R0402-PAD-1]  85.21 213.56 270 top
PR4411  1K5R2F-2-GP  [R402H16]  84.36 215.65 270 bottom
PR4412  49K9R2F-L-GP  [R402H16]  53.63 62.87 270 bottom
PR4413  0R0402-PAD-2-GP  [0R0402-PAD-1]  74.58 217.2 180 top
PR4414  62KR2F-GP  [R402H16]  76.11 216.69 90 top
PR4415  56K2R2F-2-GP  [R402H16]  81.64 218.54 0 top
PR4416  10R2F-L-GP  [R402H14]  74.09 222.09 270 top
PR4417  330KR3F-GP  [R603H22]  74.42 223.29 270 top
PR4418  4K02R2F-GP  [R402H16]  81.69 221.36 90 bottom
PR4419  75KR2F-GP  [R402H16]  79.39 223.74 0 top
PR4420  150KR2F-L-GP  [R402H16]  76.37 223.73 180 top
PR4421  2D2R6J-3-GP  [R1206H28]  67.95 208.99 0 bottom
PR4422  10KR2J-3-GP  [R402H16]  54.54 205.08 270 bottom
PR4423  2D2R6J-3-GP  [R1206H28]  52.47 206.88 0 bottom
PR4424  2D2R6J-3-GP  [R1206H28]  73.19 212.01 270 bottom
PR4425  3K3R2J-3-GP  [R402H16]  53.63 58.42 90 bottom
PR4426  3K3R2J-3-GP  [R402H16]  53.63 59.56 90 bottom
PR4427  100KR2J-1-GP  [R402H16]  50.71 62.41 180 bottom
PR4428  1R5J-2-GP  [R805H24]  74.4 221.18 180 bottom
PR4429  1KR2J-1-GP  [R402H16]  76.36 213.39 180 top
PR4430  2D2R3J-2-GP  [R603H22]  85.4 211.71 0 bottom
PR4431  0R2J-2-GP  [R402H16]  77.58 218.54 0 top
PR4432  22K1R2F-L-GP  [R402H16]  78.72 218.54 0 top
PR4433  18K7R2F-GP  [R402H16]  82.28 217.07 270 top
PR4450  10KR2F-2-GP  [R402H16]  58.68 73.94 90 top
PR4451  680KR2F-GP  [R402H16]  47.25 72.2 180 top
PR4455  0R2J-2-GP  [R402H16]  61.42 71.74 180 top
PR4458  0R2J-2-GP  [R402H16]  59.82 70.54 180 top
PR4462  0R2J-2-GP  [R402H16]  48.28 72.2 180 top
PR4490  -  [0R0805-PAD]  55.72 219.61 180 bottom
PR4491  -  [0R0805-PAD]  57.75 219.61 180 bottom
PR4492  -  [0R0805-PAD]  61.9 68.69 270 bottom
PR4493  -  [0R0805-PAD]  62.11 68.04 90 top
PR4501  1KR2J-1-GP  [R402H16]  21.55 161.82 270 bottom
PR4502  10KR2J-3-GP  [R402H16]  21.55 162.86 270 bottom
PR4503  10KR2J-3-GP  [R402H16]  23.5 163.86 270 bottom
PR4504  47R2F-GP  [R402H16]  25.18 167.89 0 top
PR4505  1KR2F-3-GP  [R402H16]  26.2 167.89 0 top
PR4506  560KR2F-GP  [R402H16]  31.56 168.4 90 top
PR4507  3K3R2F-2-GP  [R402H16]  27.72 168.35 270 top
PR4510  0R0402-PAD-2-GP  [0R0402-PAD-1]  21.14 167.89 0 top
PR4511  1K5R2F-2-GP  [R402H16]  23.15 167.89 180 top
PR4513  0R0402-PAD-2-GP  [0R0402-PAD-1]  27.01 157.76 180 top
PR4514  62KR2F-GP  [R402H16]  27.54 156.16 90 top
PR4515  45K3R2F-L-GP  [R402H16]  28.18 163.83 90 bottom
PR4516  10R2F-L-GP  [R402H14]  33.82 160.15 90 top
PR4517  100KR3F-GP  [R603H22]  34.2 161.29 270 top
PR4518  4K99R2F-L-GP  [R402H16]  30.51 163.83 0 top
PR4519  75KR2F-GP  [R402H16]  33.82 163.45 270 top
PR4520  150KR2F-L-GP  [R402H16]  33.82 162.43 90 top
PR4521  2D2R6J-3-GP  [R1206H28]  31.55 154.79 90 bottom
PR4522  10KR2J-3-GP  [R402H16]  34.58 142.37 0 bottom
PR4523  2D2R6J-3-GP  [R1206H28]  33.46 139.37 90 bottom
PR4524  2D2R6J-3-GP  [R1206H28]  20.94 158.17 90 top
PR4528  1R5J-2-GP  [R805H24]  32.14 156.92 180 top
PR4529  1KR2J-1-GP  [R402H16]  22.61 159.54 270 bottom
PR4530  2D2R3J-2-GP  [R603H22]  23.7 166.16 270 bottom
PR4531  48D7KR2F-GP  [R402H16]  29.04 157.76 0 top
PR4532  34K8R2F-1-GP  [R402H16]  31.63 159.31 90 top
PR4533  18K7R2F-GP  [R402H16]  30.47 166.03 90 top
PR4590  -  [0R0805-PAD]  22.53 140.31 0 bottom
PR4591  -  [0R0805-PAD]  24.49 140.31 0 bottom
PR4701  2D2R5J-1-GP  [R805H24]  131.62 116.86 90 top
PR4702  470KR2F-GP  [R402H16]  134.21 115.15 270 top
PR4706  0R0805-PAD-2-GP-U  [0R0805-PAD-1-U]  106.03 116.51 270 top
PR4707  0R0805-PAD-2-GP-U  [0R0805-PAD-1-U]  106.03 114.55 270 top
PR4708  0R0805-PAD-2-GP-U  [0R0805-PAD-1-U]  106.03 112.6 270 top
PR4709  0R0805-PAD-2-GP-U  [0R0805-PAD-1-U]  106.03 110.64 270 top
PR4712  10KR2J-3-GP  [R402H16]  137.29 108.58 270 top
PR4713  2D2R5J-1-GP  [R805H24]  123.65 114.48 90 top
PR4714  2D2R5J-1-GP  [R805H24]  131.27 109.98 90 top
PR4715  10KR2J-3-GP  [R402H16]  122.69 106.3 180 bottom
PR4716  2D2R5J-1-GP  [R805H24]  125.03 106.32 270 bottom
PR4717  3K6R2F-GP  [R402H16]  137.91 115.4 180 top
PR4718  10KR2F-2-GP  [R402H16]  135.12 116.4 270 top
PR4790  -  [0R0805-PAD]  131.22 105.84 270 top
PR4791  -  [0R0805-PAD]  131.22 107.82 270 top
PR4812  10KR2J-3-GP  [R402H16]  98.85 216.09 180 top
PR4901  100KR2J-1-GP  [R402H16]  65.76 55.68 180 top
PR4902  2D2R5J-1-GP  [R805H24]  60.18 54.38 180 top
PR4903  2D2R5J-1-GP  [R805H24]  61.04 65 180 top
PR4904  -  [0R0805-PAD]  78.06 50.7 90 bottom
PR4905  -  [0R0805-PAD]  77.1 62.87 90 bottom
PR4906  -  [0R0805-PAD]  98.13 52.5 270 top
PR4907  -  [0R0805-PAD]  97.57 69.88 270 top
PR4908  -  [0R0805-PAD]  98.13 50.47 270 top
PR4909  -  [0R0805-PAD]  97.57 67.92 270 top
PR4910  -  [0R0805-PAD]  98.13 54.53 270 top
PR4911  2D2R5J-1-GP  [R805H24]  77.17 58.29 270 top
PR4912  2D2R5J-1-GP  [R805H24]  78.89 70.13 270 top
PR4913  -  [0R0805-PAD]  97.57 65.96 270 top
PR4914  6K65R2F-GP  [R402H16]  58.28 56.92 180 top
PR4915  -  [0R0805-PAD]  97.57 64.01 270 top
PR4916  -  [0R0805-PAD]  97.57 61.98 270 top
PR4917  10KR2F-2-GP  [R402H16]  57.84 58.45 270 top
PR4918  56K2R2F-2-GP  [R402H16]  66.93 58.3 270 top
PR4919  68KR2F-GP  [R402H16]  60.41 59.34 0 bottom
PR4920  110KR2F-GP  [R402H16]  66.93 57.16 90 top
PR4921  15KR2F-GP  [R402H16]  58.4 61.14 180 top
PR4922  10KR2F-2-GP  [R402H16]  57.97 59.59 270 top
PR4923  100KR2J-1-GP  [R402H16]  57.77 55.42 90 top
PR4924  118KR2F-1-GP  [R402H16]  60.86 56.93 270 bottom
PR4925  110KR2F-GP  [R402H16]  60.62 60.79 270 bottom
PR4926  -  [0R0805-PAD]  97.57 59.94 270 top
PR4990  -  [0R0805-PAD]  61.9 64.78 270 bottom
PR4991  -  [0R0805-PAD]  61.9 66.73 270 bottom
PR5001  10KR2F-2-GP  [R402H16]  145.98 129.49 270 top
PR5002  10KR2J-3-GP  [R402H16]  148.09 157.4 90 top
PR5003  -  [0R0805-PAD]  140.5 166.37 90 bottom
PR5004  -  [0R0805-PAD]  140.5 164.34 90 bottom
PR5005  -  [0R0805-PAD]  140.5 162.31 90 bottom
PR5006  -  [0R0805-PAD]  140.5 160.35 90 bottom
PR5007  -  [0R0805-PAD]  140.5 158.37 90 bottom
PR5008  -  [0R0805-PAD]  140.5 156.41 90 bottom
PR5009  750KR2F-GP  [R402H16]  151.26 129.95 90 top
PR5010  100KR2J-1-GP  [R402H16]  154.92 130.48 90 bottom
PR5011  2D2R5J-1-GP  [R805H24]  156.14 138.02 270 top
PR5012  -  [0R0805-PAD]  146.49 139.27 90 top
PR5013  -  [0R0805-PAD]  149.46 139.06 180 top
PR5014  -  [0R0402-PAD]  146.41 133.05 0 top
PR5015  6K2R2F-GP  [R402H16]  153.25 133.58 0 bottom
PR5016  8K06R2F-GP  [R402H16]  146.41 131.11 0 top
PR5017  2D2R6J-3-GP  [R1206H28]  152.18 154.25 180 bottom
PR5018  2D2R5J-1-GP  [R805H24]  148.06 154.97 180 bottom
PR5019  2D2R5J-1-GP  [R805H24]  151.47 139.06 0 top
PR5090  -  [0R0805-PAD]  146.99 144.13 180 top
PR5091  -  [0R0805-PAD]  145 144.12 180 top
PR5109  -  [0R0603-PAD]  163.77 75.54 0 bottom
PR5110  -  [0R0402-PAD]  168.46 89.59 90 bottom
PR5112  10KR2F-2-GP  [R402H16]  165.34 77.27 180 bottom
PR5113  8K66R2F-GP  [R402H16]  165.16 79.83 270 bottom
PR5209  -  [0R0603-PAD]  50.33 175.69 270 top
PR5211  5K49R2F-GP  [R402H16]  49.51 172.26 0 top
PR5212  10KR2F-2-GP  [R402H16]  48.98 170.69 270 top
PR5213  10KR2J-3-GP  [R402H16]  37.57 169.32 90 top
PR5214  1KR2J-1-GP  [R402H16]  48.27 218.64 180 top
PR5216  -  [0R0402-PAD]  39.53 167.18 270 top
PR5220  0R0402-PAD-2-GP  [0R0402-PAD-1]  73.32 207.19 270 bottom
PR5221  0R0402-PAD-2-GP  [0R0402-PAD-1]  80.96 206.27 0 bottom
PR5222  0R0402-PAD-2-GP  [0R0402-PAD-1]  77.6 206.27 0 bottom
PR5232  0R0402-PAD-2-GP  [0R0402-PAD-1]  79.79 206.27 0 bottom
PR5233  0R0402-PAD-2-GP  [0R0402-PAD-1]  74.55 208.72 0 bottom
PR5234  0R0402-PAD-2-GP  [0R0402-PAD-1]  78.7 206.27 0 bottom
PR5241  1KR2J-1-GP  [R402H16]  37.57 168.17 90 top
PR5242  10KR2F-2-GP  [R402H16]  34.3 176.1 270 top
PR5243  -  [0R0603-PAD]  35.85 181.13 0 top
PR5245  -  [0R0402-PAD]  24.06 173.76 0 top
PR5246  10KR2J-3-GP  [R402H16]  22.54 175.39 90 top
PR5247  0R2J-2-GP  [R402H16]  44 16.23 180 bottom
PR5248  0R2J-2-GP  [R402H16]  45.04 16.23 180 bottom
PR5249  0R2J-2-GP  [R402H16]  41.97 13.61 180 bottom
PR5250  0R2J-2-GP  [R402H16]  43.04 13.61 180 bottom
PR5251  1KR2J-1-GP  [R402H16]  121.93 81.36 270 top
PR5254  0R0402-PAD-2-GP  [0R0402-PAD-1]  48.39 222.05 90 top
PR5257  1KR2J-1-GP  [R402H16]  22.54 174.29 90 top
PR5258  10KR2J-3-GP  [R402H16]  160.23 90.63 0 bottom
PR5261  0R0402-PAD-2-GP  [0R0402-PAD-1]  64.38 130.94 90 top
PR5268  33KR2F-GP  [R402H16]  53.12 56.39 0 bottom
PR5269  D01R3721F-GP-U  [R3720H40]  36.89 66.03 180 top
PR5270  316KR3F-2-GP  [R603H22]  53.88 65.02 90 bottom
PR5272  49K9R2F-L-GP  [R402H16]  51.56 41.16 270 top
PR5273  100KR2J-1-GP  [R402H16]  55.91 59.56 270 bottom
PR5274  -  [0R0402-PAD]  45.93 66.98 0 top
PR5275  100KR2J-1-GP  [R402H16]  52.51 42.2 270 top
PR5276  D01R3721F-GP-U  [R3720H40]  52.43 45.5 270 top
PR5277  7D5R2F-GP  [R402H16]  49.44 54 180 top
PR5278  100KR2J-1-GP  [R402H16]  52.99 54.36 0 bottom
PR5279  1D5R2F-GP  [R402H16]  43.21 57.78 270 top
PR5281  100KR2J-1-GP  [R402H16]  56.37 62.23 180 top
PR5282  10KR2F-2-GP  [R402H16]  51.56 40.13 270 top
PR5283  10R2F-L-GP  [R402H14]  48.26 54.04 180 top
PR5284  20R5F-1GP  [R805H24]  43.05 65.2 180 bottom
PR5285  470KR2J-2-GP  [R402H16]  41.83 74.16 270 top
PR5286  10KR2F-2-GP  [R402H16]  51.85 54.36 180 bottom
PR5287  3D3MR2J-GP  [R402H16]  48.38 63.7 90 top
PR5288  -  [0R0402-PAD]  53.63 60.71 270 bottom
PR5289  100KR2J-1-GP  [R402H16]  48.29 62.61 90 bottom
PR5290  -  [0R0603-PAD]  90.65 224.26 270 top
PR5291  -  [0R0603-PAD]  90.66 222.84 270 top
PR5297  100KR2J-1-GP  [R402H16]  46.65 64.17 0 bottom
PR5298  120KR2F-L-GP  [R402H16]  46.18 65.63 270 bottom
PR5467  102KR2F-GP  [R402H16]  51.09 63.5 270 top
PR5468  169KR2F-1-GP  [R402H16]  49.56 65.28 180 top
PR5469  78K7R2F-GP  [R402H16]  50.71 65.28 0 top
PR5470  309KR2F-GP  [R402H16]  48.42 65.28 180 top
PR5471  -  [0R0805-PAD]  94.06 203.4 0 top
PR5473  18KR2F-GP  [R402H16]  99.68 224.33 90 top
PR5474  2D2R5J-1-GP  [R805H24]  92.37 218.43 270 top
PR5475  2D2R5J-1-GP  [R805H24]  93.91 223.95 90 top
PR5476  0R2J-2-GP  [R402H16]  115.64 80.33 180 top
PR5479  0R0402-PAD-2-GP  [0R0402-PAD-1]  44.91 220.6 180 top
PR5480  1KR2J-1-GP  [R402H16]  44.91 218.67 180 top
PR8519  3K3R2J-3-GP  [R402H16]  137.12 68.43 0 bottom
PR8520  3K3R2J-3-GP  [R402H16]  138.51 68.83 0 bottom
PR8521  0R2J-2-GP  [R402H16]  125.81 71.28 270 bottom
PR9766  100R2J-2-GP  [R402H14]  52.97 188.57 180 top
PR9767  -  [0R0603-PAD]  34.3 181.12 0 top
PR9768  1KR2J-1-GP  [R402H16]  121.67 89.06 270 top
PR9769  1KR2J-1-GP  [R402H16]  117.58 85.85 90 top
PR9770  1KR2J-1-GP  [R402H16]  121.67 87.95 270 top
PR9771  1R2F-GP  [R402H16]  131.92 85 270 bottom
PR9772  1KR2J-1-GP  [R402H16]  117.61 89.11 90 top
PR9773  -  [0R0402-PAD]  124.26 86.63 90 top
PR9774  -  [0R0402-PAD]  124.26 87.73 90 top
PR9775  1KR2J-1-GP  [R402H16]  118.93 81.23 90 top
PR9776  1KR2J-1-GP  [R402H16]  118.88 84.41 90 top
PR9777  0R0603-PAD-2-GP-U  [0R0603-PAD-1-U]  134.25 85.04 90 bottom
PR9778  9K31R2F-GP  [R402H16]  136.13 84.59 0 bottom
PR9779  1R2F-GP  [R402H16]  142.15 86.86 90 top
PR9780  1KR2J-1-GP  [R402H16]  121.67 86.84 270 top
PR9781  11KR2F-L-GP  [R402H16]  138.35 86.09 0 top
PR9782  4K02R2F-GP  [R402H16]  138.82 88.32 90 top
PR9783  2D2R5J-1-GP  [R805H24]  129.93 97.21 90 top
PR9785  0R2J-2-GP  [R402H16]  141.82 110.78 0 top
PR9787  1KR2J-1-GP  [R402H16]  139.5 110.52 180 top
PR9788  -  [0R0805-PAD]  48.47 209.02 270 top
PR9789  -  [0R0805-PAD]  48.47 211.01 270 top
PR9790  0R0805-PAD-2-GP-U  [0R0805-PAD-1-U]  51.46 188.12 0 top
PR9791  0R0805-PAD-2-GP-U  [0R0805-PAD-1-U]  49.5 188.12 0 top
PR9792  0R0805-PAD-2-GP-U  [0R0805-PAD-1-U]  47.55 188.12 0 top
PR9793  2D2R5J-1-GP  [R805H24]  36.71 218.03 180 top
PR9794  2D2R5J-1-GP  [R805H24]  42.86 216.41 180 top
PR9795  5K11R2F-L1-GP  [R402H16]  36.78 224.07 90 top
PR9796  10KR2F-2-GP  [R402H16]  36.42 221.68 0 top
PR9797  2D2R5J-1-GP  [R805H24]  48.12 201.32 180 top
PR9798  10KR2J-3-GP  [R402H16]  45.58 198.65 90 top
PR9799  0R0805-PAD-2-GP-U  [0R0805-PAD-1-U]  45.42 188.12 0 top
PR9800  0R0805-PAD-2-GP-U  [0R0805-PAD-1-U]  43.46 188.12 0 top
PR9801  0R0805-PAD-2-GP-U  [0R0805-PAD-1-U]  41.48 188.12 0 top
PR9802  0R0805-PAD-2-GP-U  [0R0805-PAD-1-U]  39.5 188.12 0 top
PR9803  10KR2J-3-GP  [R402H16]  43.85 220.6 180 top
PR9804  470KR2F-GP  [R402H16]  37.47 221.67 0 top
PR9805  2D2R5J-1-GP  [R805H24]  36.94 201.07 180 top
PR9806  0R0402-PAD-2-GP  [0R0402-PAD-1]  64.06 141.74 180 top
PR9807  0R0402-PAD-2-GP  [0R0402-PAD-1]  75.58 133.95 180 top
PR9808  0R0402-PAD-2-GP  [0R0402-PAD-1]  74.46 133.95 180 top
PR9809  0R0402-PAD-2-GP  [0R0402-PAD-1]  67.16 139.66 90 top
PR9810  0R0402-PAD-2-GP  [0R0402-PAD-1]  81.09 137.22 270 top
PR9811  0R0402-PAD-2-GP  [0R0402-PAD-1]  78.94 136.76 180 top
PR9812  100KR2F-L1-GP  [R402H16]  58.66 72.85 270 top
PR9813  100KR2J-1-GP  [R402H16]  49.45 74.42 90 top
PR9814  1MR2J-1-GP  [R402H16]  51.37 74.38 90 top
PSWD1  JOWLE-CON2-5-GP  [A2541WV0-1EX2PA-6T]  150.6 171.9 270 top
PT1  E820U2D5VM-14-GP  [ECAP-100D6D3H355]  109 90.2 0 top
PT2  SE47U25VM-14-GP  [SE361416H237]  145.37 96.9 0 top
PT3  E820U2D5VM-14-GP  [ECAP-100D6D3H355]  109.02 105.94 0 top
PT4  E820U2D5VM-14-GP  [ECAP-100D6D3H355]  109.02 98.07 0 top
PT4491  SE47U25VM-14-GP  [SE361416H237]  59.8 211.15 90 top
PT4591  SE47U25VM-14-GP  [SE361416H237]  21.6 149.02 180 top
PT4901  SE47U25VM-13-GP  [SE361414H241]  69.97 64.96 180 top
PT4902  SE220U6D3VM-8GP  [SE331721H237]  92.11 53.97 180 top
PT4903  SE220U6D3VM-8GP  [SE331721H237]  91.94 63.85 0 top
PT5001  SE47U25VM-14-GP  [SE361416H237]  152.71 144.75 90 top
PT5002  SE47U25VM-14-GP  [SE361416H237]  41.98 210.7 270 top
PTC9  E820U2D5VM-7-GP  [ECAP-100D6D3H355]  26.98 189.18 0 top
PTC21  E820U2D5VM-7-GP  [ECAP-100D6D3H355]  146.57 162.05 270 top
PTC4701  E820U2D5VM-7-GP  [ECAP-100D6D3H355]  114.13 116.66 0 top
PTC4702  E820U2D5VM-7-GP  [ECAP-100D6D3H355]  47.96 194.44 0 top
PU1  AON6552-GP  [PPAK-8P-5262H40]  132.6 101.52 270 top
PU2  AON6552-GP  [PPAK-8P-5262H40]  132.6 101.52 90 bottom
PU3  AON6508-GP  [PPAK-8P-5262H40]  130.56 92.89 90 top
PU4  RT8237CZQW-2-GP  [DFN10G3-G265175H32]  16.04 220.42 90 top
PU7  APL5912-KAC-TRG-GP  [SOIC8-G3530H63]  57.24 129.3 270 top
PU4201  AO4407AL-GP  [SOIC8H69]  65.46 39.03 0 top
PU4401  NCP81201MNTXG-GP  [LFQFN28J4-G2D7H40]  79.54 215.77 0 bottom
PU4403  AON7410-GP  [PPAK-8P-3232H36]  35.66 54.84 0 bottom
PU4405  AON7410-GP  [PPAK-8P-3232H36]  40.07 56.34 180 bottom
PU4501  NCP81201MNTXG-GP  [LFQFN28J4-G2D7H40]  25.69 163.07 90 top
PU4502  AON6520-GP  [PPAK-8P-5262H40]  28.66 143.81 270 bottom
PU4503  AON6510-GP  [PPAK-8P-5262H40]  30.39 150.39 270 top
PU4504  AON6510-GP  [PPAK-8P-5262H40]  30.42 150.39 90 bottom
PU4701  RT8237CZQW-2-GP  [DFN10G3-G265175H32]  40.09 220.9 0 top
PU4705  RT8237CZQW-2-GP  [DFN10G3-G265175H32]  135.64 112.12 270 top
PU4901  RT8243AZQW-GP  [QFN20-G1D75H32]  62.16 59.56 90 top
PU5001  RT8207MZQW-GP-U  [QFN20-G1D75H32]  151.7 133.88 90 top
PU5201  APL5930KAI-TRG-1-GP  [SOIC8-G3530H63]  44 172.19 90 top
PU5202  APL5930KAI-TRG-1-GP  [SOIC8-G3530H63]  165.18 84.31 180 bottom
PU5203  APL5930KAI-TRG-1-GP  [SOIC8-G3530H63]  29.03 177.48 90 top
PU5204  AO4407AL-GP  [SOIC8H69]  58.53 43.12 270 top
PU5205  AO4407AL-GP  [SOIC8H69]  38.02 70.77 90 top
PU5206  RT8068AZQWID-GP-U  [DFN10G3-G265175H32]  96.18 220 180 top
PU5207  AON6508-GP  [PPAK-8P-5262H40]  130.57 92.9 270 bottom
PWRCN1  ACES-CON10-30-GP  [51530-01041-W01]  26.75 22.5 270 top
Q1  2N7002A-7-GP  [SOT23DGS2D4H48]  37.96 111.61 90 bottom
Q3  2N7002A-7-GP  [SOT23DGS2D4H48]  131.35 214.5 270 bottom
Q4  2N7002KDW-1-GP  [SOT-363H44]  37.04 76.1 270 bottom
Q5  2N7002A-7-GP  [SOT23DGS2D4H48]  37.96 115.21 90 bottom
Q7  2N7002KDW-1-GP  [SOT-363H44]  32.57 75.59 270 bottom
Q10  MMBT3904-4-GP  [SOT23CBE2D4H44]  34.07 118.11 180 bottom
Q12  MMBT3904DW-GP  [SOT-363H44]  58.82 77.9 270 top
Q13  MMBT3904DW-GP  [SOT-363H44]  50.4 77.85 90 top
Q16  MMBT3904DW-GP  [SOT-363H44]  94.33 125.88 90 top
Q17  MMBT3904DW-GP  [SOT-363H44]  107.04 119.66 270 top
Q18  MMBT3904-4-GP  [SOT23CBE2D4H44]  104.99 66.52 180 top
Q19  LMBT3904LT1G-GP  [SOT23CBE2D4H44]  30.39 15.2 90 top
Q20  MMBT3904DW-GP  [SOT-363H44]  28.96 179.91 90 bottom
Q21  MMBT3904DW-GP  [SOT-363H44]  43.16 119.28 0 top
Q23  2N7002EDW-2-GP  [SOT-363H44]  151.97 209.55 90 top
Q24  AZ5125-02S-R7G-GP  [SOT23-2D4-312H46]  167.49 74.56 90 top
Q28  2N7002-11-GP  [SOT23DGS2D4H44]  154.82 58.19 0 bottom
Q29  2N7002EDW-2-GP  [SOT-363H44]  131.58 60.17 180 bottom
Q30  2N7002KDW-GP  [SOT-363H44]  141.49 63.96 180 top
Q35  MMBT3904DW-GP  [SOT-363H44]  31.22 17.17 180 bottom
Q36  MMBT3904-4-GP  [SOT23CBE2D4H44]  27.8 16.41 270 bottom
Q37  MMBT3904-4-GP  [SOT23CBE2D4H44]  23.96 14.02 90 bottom
Q38  MMBT3904-4-GP  [SOT23CBE2D4H44]  23.93 17.63 270 bottom
Q39  AO3413L-GP  [SOT23DGS2D8H50]  31.48 9.47 90 bottom
Q40  MMBT3904-4-GP  [SOT23CBE2D4H44]  46.67 25.02 0 top
Q42  2N7002A-7-GP  [SOT23DGS2D4H48]  46.08 19.2 270 top
Q46  AZ5125-02S-R7G-GP  [SOT23-2D4-312H46]  85.15 38.73 270 top
Q47  PMBS3904-1-GP  [SOT-23-10H44]  42.4 20.65 270 bottom
Q48  2N7002KDW-GP  [SOT-363H44]  151.87 129.34 90 bottom
Q49  2N7002KDW-GP  [SOT-363H44]  99.55 131.63 180 top
Q51  MMBT3904-4-GP  [SOT23CBE2D4H44]  158.67 140.07 0 bottom
Q56  2N7002A-7-GP  [SOT23DGS2D4H48]  151.37 47.85 90 top
Q57  AZ5125-02S-R7G-GP  [SOT23-2D4-312H46]  167.49 78.5 90 top
Q63  MMBT3904DW-GP  [SOT-363H44]  149.05 39.09 270 bottom
Q64  2N7002A-7-GP  [SOT23DGS2D4H48]  145.37 38.73 0 bottom
Q65  2N7002A-7-GP  [SOT23DGS2D4H48]  27.82 20.02 90 bottom
Q66  2N7002H-GP  [SOT23DGS2D4H44]  114.61 65.47 90 bottom
Q68  2N7002A-7-GP  [SOT23DGS2D4H48]  23.93 21.23 90 bottom
Q74  MMBT3904-4-GP  [SOT23CBE2D4H44]  43.09 6.99 0 bottom
Q75  MMBT3904-4-GP  [SOT23CBE2D4H44]  47.66 6.93 0 top
Q76  MMBT3904-4-GP  [SOT23CBE2D4H44]  42.6 8.25 0 top
Q77  2N7002H-GP  [SOT23DGS2D4H44]  97.92 123.88 0 top
Q78  2N7002H-GP  [SOT23DGS2D4H44]  101.61 124.69 270 top
Q79  2N7002H-GP  [SOT23DGS2D4H44]  106.61 123.32 270 top
Q95  2N7002KDW-1-GP  [SOT-363H44]  47.62 76.73 0 bottom
Q97  2N7002KDW-1-GP  [SOT-363H44]  75.65 117.65 0 top
Q103  2N7002A-7-GP  [SOT23DGS2D4H48]  41.9 117.07 180 bottom
Q123  2N7002KDW-1-GP  [SOT-363H44]  103.41 96.39 0 top
Q1203  DMN5L06K-7-GP  [SOT23DGS2D4H48]  146.97 193.04 270 bottom
Q1204  DMN5L06K-7-GP  [SOT23DGS2D4H48]  145.98 189.43 270 bottom
Q1205  2N7002H-GP  [SOT23DGS2D4H44]  154.72 182.88 90 top
Q1206  MMBT3904DW-GP  [SOT-363H44]  88.91 126.75 180 top
Q1209  AO3413L-GP  [SOT23DGS2D8H50]  127.16 210.06 0 bottom
Q1210  DMN5L06K-7-GP  [SOT23DGS2D4H48]  127.49 219.02 180 bottom
Q1212  DMN5L06K-7-GP  [SOT23DGS2D4H48]  142.02 189.41 90 bottom
Q1213  DMN5L06K-7-GP  [SOT23DGS2D4H48]  141.97 193.01 90 bottom
Q1214  2N7002H-GP  [SOT23DGS2D4H44]  92.75 121.13 180 top
Q1227  2N7002H-GP  [SOT23DGS2D4H44]  21.75 197.61 180 bottom
Q1228  2N7002KDW-GP  [SOT-363H44]  47.4 183.4 270 bottom
Q1229  2N7002KDW-GP  [SOT-363H44]  83.47 221.02 270 top
Q1230  2N7002KDW-GP  [SOT-363H44]  47.38 179.77 90 bottom
Q1231  2N7002KDW-GP  [SOT-363H44]  38.74 184.23 90 bottom
Q1232  2N7002KDW-GP  [SOT-363H44]  38.74 180.64 90 bottom
Q1233  2N7002KDW-GP  [SOT-363H44]  49.26 216.81 180 bottom
Q1234  2N7002H-GP  [SOT23DGS2D4H44]  48.37 220.57 0 bottom
Q1236  PMBS3904-1-GP  [SOT-23-10H44]  105.01 222.71 270 bottom
Q1240  AO3413L-GP  [SOT23DGS2D8H50]  147.73 132.97 180 bottom
Q1246  2N7002A-7-GP  [SOT23DGS2D4H48]  74.27 191.39 270 top
Q1250  AO4286-GP  [SOIC8H69]  35.72 39.8 270 bottom
Q1253  PMBS3904-1-GP  [SOT-23-10H44]  84.54 137.8 0 top
Q1254  2N7002A-7-GP  [SOT23DGS2D4H48]  142.58 31.65 270 bottom
Q1255  DMN5L06K-7-GP  [SOT23DGS2D4H48]  127.39 27.91 270 bottom
Q1256  DMN5L06K-7-GP  [SOT23DGS2D4H48]  131.35 25.93 270 bottom
Q1257  2N7002A-7-GP  [SOT23DGS2D4H48]  127.39 24.31 90 bottom
Q2301  2N7002A-7-GP  [SOT23DGS2D4H48]  126.49 43.93 0 top
Q6701  2N7002KDW-GP  [SOT-363H44]  18.43 186.08 90 top
Q6702  PMBS3904-1-GP  [SOT-23-10H44]  93.91 39.19 0 top
Q6703  2N7002A-7-GP  [SOT23DGS2D4H48]  74.27 187.78 270 top
Q6705  AO3418L-GP  [SOT23DGS2D8H50]  146.31 220.04 90 top
Q6706  2N7002H-GP  [SOT23DGS2D4H44]  138.67 46.84 90 top
Q6708  LMBT3904LT1G-GP  [SOT23CBE2D4H44]  131.33 218.16 270 bottom
Q6710  LMBT3904LT1G-GP  [SOT23CBE2D4H44]  41.18 24.89 0 top
Q6711  LMBT3904LT1G-GP  [SOT23CBE2D4H44]  149.94 49.25 180 bottom
